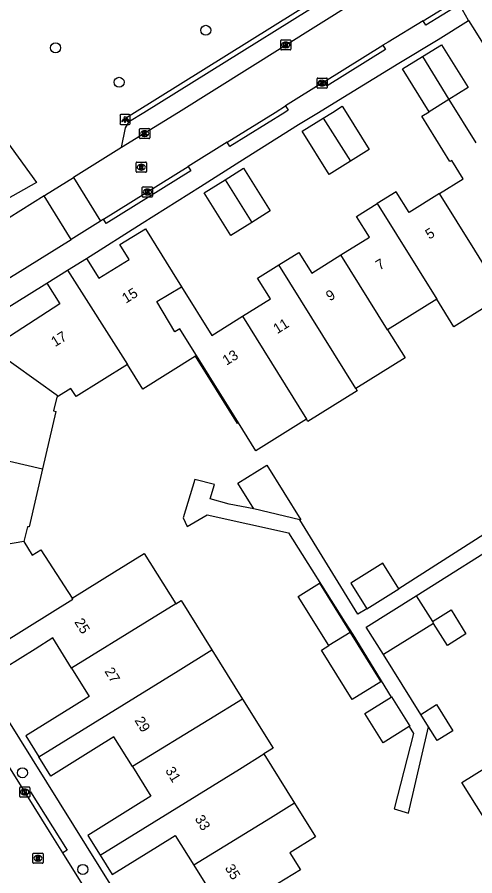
# Model space of a CAD drawing. Extents: x 157767 to 159171, y 387842 to 389425.
# Drawn here: x 158455.1 to 158500, y 387925 to 388009.4 of the extents above; entities that cross this region are included whole.
import ezdxf

# ---------------------------------------------------------------- set-up
doc = ezdxf.new("R2010")
doc.units = 0
for name, color, linetype in [('IMGEO_Boom', 7, 'Continuous'), ('IMGEO_Groenvoorziening', 7, 'Continuous'), ('IMGEO_Kolk', 7, 'Continuous'), ('IMGEO_Lichtpunt', 7, 'Continuous'), ('IMGEO_Pand', 7, 'Continuous'), ('IMGEO_Pand_nummerreeks', 7, 'Continuous'), ('IMGEO_Parkeervlak_open', 7, 'Continuous'), ('IMGEO_Rijbaan_lokaal_open', 7, 'Continuous'), ('IMGEO_Rioolput', 7, 'Continuous'), ('IMGEO_Voetpad_open', 7, 'Continuous')]:
    doc.layers.add(name, color=color, linetype=linetype)

msp = doc.modelspace()

# ---------------------------------------------------------------- linework, layer by layer
at = {"layer": 'IMGEO_Boom'}
for centre in [(158473.576, 388008.067), (158458.821, 388006.342), (158465.063, 388002.96), (158455.572, 387935.087), (158461.501, 387925.585)]:
    msp.add_circle(centre, 0.489, dxfattribs=at)
at = {"layer": 'IMGEO_Groenvoorziening'}
msp.add_lwpolyline([(158397.502, 388074.3), (158401.091, 388069.402), (158451.954, 388000), (158456.939, 387993.105), (158446.112, 387987.022)], dxfattribs=at)
at = {"layer": 'IMGEO_Kolk'}
for p, q in [((158480.933, 388006.207), (158480.933, 388007.059)), ((158481.008, 388007.133), (158481.86, 388007.133)), ((158481.934, 388007.059), (158481.934, 388006.207)), ((158481.86, 388006.133), (158481.008, 388006.133)), ((158481.444, 388006.353), (158481.419, 388006.353)), ((158481.421, 388006.913), (158481.446, 388006.913)), ((158484.504, 388002.449), (158484.504, 388003.301)), ((158484.579, 388003.375), (158485.431, 388003.375)), ((158484.992, 388003.155), (158485.017, 388003.155)), ((158485.505, 388003.301), (158485.505, 388002.449)), ((158485.431, 388002.375), (158484.579, 388002.375)), ((158485.015, 388002.595), (158484.99, 388002.595)), ((158467.073, 387997.491), (158467.073, 387998.343)), ((158467.148, 387998.417), (158468, 387998.417)), ((158467.561, 387998.197), (158467.586, 387998.197)), ((158468.074, 387998.343), (158468.074, 387997.491)), ((158468, 387997.417), (158467.148, 387997.417)), ((158467.584, 387997.637), (158467.559, 387997.637)), ((158467.342, 387991.748), (158467.342, 387992.6)), ((158467.417, 387992.674), (158468.269, 387992.674)), ((158468.343, 387992.6), (158468.343, 387991.748)), ((158467.853, 387991.894), (158467.828, 387991.894)), ((158467.83, 387992.454), (158467.855, 387992.454)), ((158468.269, 387991.674), (158467.417, 387991.674)), ((158455.301, 387932.772), (158455.301, 387933.624)), ((158455.376, 387933.698), (158456.228, 387933.698)), ((158456.302, 387933.624), (158456.302, 387932.772)), ((158456.228, 387932.698), (158455.376, 387932.698)), ((158455.812, 387932.918), (158455.787, 387932.918)), ((158455.789, 387933.478), (158455.814, 387933.478))]:
    msp.add_line(p, q, dxfattribs=at)
for points in [[(158480.933, 388006.207), (158480.933, 388007.059)], [(158481.008, 388007.133), (158481.86, 388007.133)], [(158481.934, 388007.059), (158481.934, 388006.207)], [(158481.86, 388006.133), (158481.008, 388006.133)], [(158481.254, 388006.833), (158481.377, 388006.833), (158481.377, 388006.682), (158481.507, 388006.833), (158481.671, 388006.833), (158481.525, 388006.682), (158481.678, 388006.433), (158481.526, 388006.433), (158481.441, 388006.597), (158481.377, 388006.53), (158481.377, 388006.433), (158481.254, 388006.433), (158481.254, 388006.833)], [(158484.504, 388002.449), (158484.504, 388003.301)], [(158484.579, 388003.375), (158485.431, 388003.375)], [(158484.825, 388003.075), (158484.948, 388003.075), (158484.948, 388002.924), (158485.078, 388003.075), (158485.242, 388003.075), (158485.096, 388002.924), (158485.249, 388002.675), (158485.097, 388002.675), (158485.012, 388002.839), (158484.948, 388002.772), (158484.948, 388002.675), (158484.825, 388002.675), (158484.825, 388003.075)], [(158485.505, 388003.301), (158485.505, 388002.449)], [(158485.431, 388002.375), (158484.579, 388002.375)], [(158467.073, 387997.491), (158467.073, 387998.343)], [(158467.148, 387998.417), (158468, 387998.417)], [(158467.394, 387998.117), (158467.517, 387998.117), (158467.517, 387997.966), (158467.647, 387998.117), (158467.811, 387998.117), (158467.665, 387997.966), (158467.818, 387997.717), (158467.666, 387997.717), (158467.581, 387997.881), (158467.517, 387997.814), (158467.517, 387997.717), (158467.394, 387997.717), (158467.394, 387998.117)], [(158468.074, 387998.343), (158468.074, 387997.491)], [(158468, 387997.417), (158467.148, 387997.417)], [(158467.342, 387991.748), (158467.342, 387992.6)], [(158467.417, 387992.674), (158468.269, 387992.674)], [(158468.343, 387992.6), (158468.343, 387991.748)], [(158467.663, 387992.374), (158467.786, 387992.374), (158467.786, 387992.223), (158467.916, 387992.374), (158468.08, 387992.374), (158467.934, 387992.223), (158468.087, 387991.974), (158467.935, 387991.974), (158467.85, 387992.138), (158467.786, 387992.071), (158467.786, 387991.974), (158467.663, 387991.974), (158467.663, 387992.374)], [(158468.269, 387991.674), (158467.417, 387991.674)], [(158455.301, 387932.772), (158455.301, 387933.624)], [(158455.376, 387933.698), (158456.228, 387933.698)], [(158456.302, 387933.624), (158456.302, 387932.772)], [(158456.228, 387932.698), (158455.376, 387932.698)], [(158455.622, 387933.398), (158455.745, 387933.398), (158455.745, 387933.247), (158455.875, 387933.398), (158456.039, 387933.398), (158455.893, 387933.247), (158456.046, 387932.998), (158455.894, 387932.998), (158455.809, 387933.162), (158455.745, 387933.095), (158455.745, 387932.998), (158455.622, 387932.998), (158455.622, 387933.398)]]:
    msp.add_lwpolyline(points, dxfattribs=at)
for centre, start, end in [((158481.01, 388007.057), 91.55205, 178.44795), ((158481.01, 388007.057), 91.55205, 178.44795), ((158481.858, 388007.057), 1.55205, 88.44795), ((158481.858, 388007.057), 1.55205, 88.44795), ((158481.01, 388006.209), 181.55205, 268.44795), ((158481.01, 388006.209), 181.55205, 268.44795), ((158481.858, 388006.209), 271.55205, 358.44795), ((158481.858, 388006.209), 271.55205, 358.44795), ((158484.581, 388003.299), 91.55205, 178.44795), ((158484.581, 388003.299), 91.55205, 178.44795), ((158485.429, 388003.299), 1.55205, 88.44795), ((158485.429, 388003.299), 1.55205, 88.44795), ((158484.581, 388002.451), 181.55205, 268.44795), ((158484.581, 388002.451), 181.55205, 268.44795), ((158485.429, 388002.451), 271.55205, 358.44795), ((158485.429, 388002.451), 271.55205, 358.44795), ((158467.15, 387998.341), 91.55205, 178.44795), ((158467.15, 387998.341), 91.55205, 178.44795), ((158467.998, 387998.341), 1.55205, 88.44795), ((158467.998, 387998.341), 1.55205, 88.44795), ((158467.15, 387997.493), 181.55205, 268.44795), ((158467.15, 387997.493), 181.55205, 268.44795), ((158467.998, 387997.493), 271.55205, 358.44795), ((158467.998, 387997.493), 271.55205, 358.44795), ((158467.419, 387992.598), 91.55205, 178.44795), ((158467.419, 387992.598), 91.55205, 178.44795), ((158468.267, 387992.598), 1.55205, 88.44795), ((158468.267, 387992.598), 1.55205, 88.44795), ((158467.419, 387991.75), 181.55205, 268.44795), ((158467.419, 387991.75), 181.55205, 268.44795), ((158468.267, 387991.75), 271.55205, 358.44795), ((158468.267, 387991.75), 271.55205, 358.44795), ((158455.378, 387933.622), 91.55205, 178.44795), ((158455.378, 387933.622), 91.55205, 178.44795), ((158456.226, 387933.622), 1.55205, 88.44795), ((158456.226, 387933.622), 1.55205, 88.44795), ((158455.378, 387932.774), 181.55205, 268.44795), ((158455.378, 387932.774), 181.55205, 268.44795), ((158456.226, 387932.774), 271.55205, 358.44795), ((158456.226, 387932.774), 271.55205, 358.44795)]:
    msp.add_arc(centre, 0.0765, start, end, dxfattribs=at)
for centre, major_axis, ratio, start_param, end_param in [((158481.42, 388006.633), (-0.387, 0.002), 0.722429, 4.712389, 7.853982), ((158481.445, 388006.633), (-0.39, 0.002), 0.717154, 1.570796, 4.712389), ((158484.991, 388002.875), (-0.387, 0.002), 0.722429, 4.712389, 7.853982), ((158485.016, 388002.875), (-0.39, 0.002), 0.717154, 1.570796, 4.712389), ((158467.56, 387997.917), (-0.387, 0.002), 0.722429, 4.712389, 7.853982), ((158467.585, 387997.917), (-0.39, 0.002), 0.717154, 1.570796, 4.712389), ((158467.829, 387992.174), (-0.387, 0.002), 0.722429, 4.712389, 7.853982), ((158467.854, 387992.174), (-0.39, 0.002), 0.717154, 1.570796, 4.712389), ((158455.788, 387933.198), (-0.387, 0.002), 0.722429, 4.712389, 7.853982), ((158455.813, 387933.198), (-0.39, 0.002), 0.717154, 1.570796, 4.712389)]:
    msp.add_ellipse(centre, major_axis=major_axis, ratio=ratio, start_param=start_param, end_param=end_param, dxfattribs=at)
at = {"layer": 'IMGEO_Lichtpunt'}
for p, q in [((158465.153, 387999.703), (158465.153, 387998.896)), ((158465.153, 387999.703), (158465.153, 387998.896)), ((158466.055, 387999.798), (158465.247, 387999.798)), ((158466.055, 387999.798), (158465.247, 387999.798)), ((158466.149, 387998.896), (158466.149, 387999.703)), ((158466.149, 387998.896), (158466.149, 387999.703)), ((158465.247, 387998.802), (158466.055, 387998.802)), ((158465.247, 387998.802), (158466.055, 387998.802))]:
    msp.add_line(p, q, dxfattribs=at)
for points in [[(158465.527, 387999.367), (158465.566, 387999.339), (158465.378, 387999.077), (158465.34, 387999.104), (158465.527, 387999.367)], [(158465.739, 387999.339), (158465.777, 387999.366), (158465.964, 387999.104), (158465.925, 387999.076), (158465.739, 387999.339)], [(158465.629, 387999.319), (158465.676, 387999.319), (158465.676, 387998.997), (158465.629, 387998.997), (158465.629, 387999.319)]]:
    msp.add_lwpolyline(points, dxfattribs=at)
msp.add_circle((158465.652, 387999.501), 0.0994, dxfattribs=at)
for centre, start, end in [((158465.247, 387999.703), 90, 180), ((158465.247, 387999.703), 90, 180), ((158466.055, 387999.703), 0, 90), ((158466.055, 387999.703), 0, 90), ((158465.247, 387998.896), 180, 270), ((158465.247, 387998.896), 180, 270), ((158466.055, 387998.896), 270, 0), ((158466.055, 387998.896), 270, 360)]:
    msp.add_arc(centre, 0.0946, start, end, dxfattribs=at)
at = {"layer": 'IMGEO_Pand'}
for points in [[(158494.857, 388005.499), (158496.713, 388006.654), (158499.333, 388002.445), (158497.453, 388001.275)], [(158495.503, 388000.062), (158492.883, 388004.271), (158494.857, 388005.499)], [(158494.857, 388005.499), (158497.453, 388001.275)], [(158497.453, 388001.275), (158495.503, 388000.062)], [(158497.453, 388001.275), (158500.098, 387997.004)], [(158485.099, 387999.43), (158486.014, 388000), (158486.985, 388000.604), (158487.361, 388000), (158489.631, 387996.351), (158487.779, 387995.198)], [(158487.779, 387995.198), (158485.706, 387993.908), (158483.059, 387998.161), (158485.099, 387999.43)], [(158485.099, 387999.43), (158487.779, 387995.198)], [(158496.531, 387992.022), (158498.858, 387993.471), (158497.731, 387995.282), (158497.552, 387995.171), (158494.785, 387999.616), (158495.503, 388000.062)], [(158475.481, 387993.383), (158477.298, 387994.513), (158479.913, 387990.31), (158478.115, 387989.191)], [(158478.115, 387989.191), (158476.038, 387987.899), (158473.422, 387992.102), (158475.481, 387993.383)], [(158475.481, 387993.383), (158478.115, 387989.191)], [(158496.531, 387992.022), (158493.542, 387990.16), (158492.272, 387992.199), (158490.412, 387991.04)], [(158502.799, 387981.952), (158501.119, 387984.652), (158500, 387986.449), (158496.531, 387992.022)], [(158486.857, 387985.983), (158489.653, 387987.725), (158488.378, 387989.773), (158490.412, 387991.04)], [(158490.412, 387991.04), (158496.272, 387981.633)], [(158461.851, 387985.648), (158463.067, 387983.695), (158466.041, 387985.547), (158465.137, 387986.999), (158467.647, 387988.562), (158470.284, 387984.327), (158471.197, 387982.861)], [(158480.747, 387985.003), (158482.723, 387986.234), (158483.991, 387984.198), (158486.857, 387985.983)], [(158491.436, 387978.622), (158486.857, 387985.983)], [(158460.011, 387984.502), (158461.851, 387985.648)], [(158477.194, 387979.957), (158479.939, 387981.666), (158478.667, 387983.708), (158480.747, 387985.003)], [(158488.319, 387972.861), (158480.747, 387985.003)], [(158457.961, 387983.225), (158460.011, 387984.502)], [(158460.011, 387984.502), (158465.877, 387975.202)], [(158457.961, 387983.225), (158459.229, 387981.189), (158452.509, 387976.838)], [(158476.789, 387969.5), (158471.03, 387978.74), (158470.53, 387978.44), (158468.77, 387981.42), (158471.197, 387982.861)], [(158471.197, 387982.861), (158474.176, 387978.077), (158477.194, 387979.957)], [(158496.272, 387981.633), (158491.436, 387978.622)], [(158502.799, 387981.952), (158497.953, 387978.935), (158496.272, 387981.633)], [(158477.194, 387979.957), (158483.485, 387969.841)], [(158491.436, 387978.622), (158493.15, 387975.879), (158488.319, 387972.861)], [(158452.509, 387976.838), (158459.127, 387972.116)], [(158476.789, 387969.5), (158476.683, 387969.434), (158472.575, 387976.03), (158467.381, 387972.796), (158465.877, 387975.202)], [(158465.877, 387975.202), (158460.842, 387972.067), (158460.34, 387972.872), (158459.127, 387972.116)], [(158488.319, 387972.861), (158488.451, 387972.64), (158483.616, 387969.629), (158483.485, 387969.841)], [(158459.127, 387972.116), (158458.953, 387972.008), (158458.638, 387970.655), (158458.866, 387970.602), (158457.554, 387964.961)], [(158483.485, 387969.841), (158478.509, 387966.733), (158476.789, 387969.5)], [(158446.814, 387967.458), (158457.554, 387964.961)], [(158457.554, 387964.961), (158456.229, 387959.261), (158456.053, 387959.255), (158455.719, 387957.819)], [(158478.292, 387961.019), (158476.713, 387963.559), (158479.562, 387965.339), (158482.921, 387959.935), (158482.812, 387959.961)], [(158482.812, 387959.961), (158478.292, 387961.019)], [(158455.719, 387957.819), (158447.698, 387956.443)], [(158455.719, 387957.819), (158456.527, 387956.474), (158457.389, 387957.01), (158460.458, 387952.25)], [(158460.458, 387952.25), (158464.629, 387954.847), (158467.535, 387956.657), (158470.624, 387951.696)], [(158492.529, 387953.174), (158490.968, 387955.681), (158487.824, 387953.724), (158489.385, 387951.217)], [(158485.662, 387947.593), (158482.651, 387952.428), (158484.736, 387953.726), (158487.747, 387948.891)], [(158489.385, 387951.217), (158492.529, 387953.174)], [(158451.184, 387946.354), (158460.52, 387952.15), (158460.458, 387952.25)], [(158491.018, 387946.7), (158489.328, 387949.413), (158494.254, 387952.481)], [(158494.254, 387952.481), (158495.834, 387949.944)], [(158470.624, 387951.696), (158467.83, 387949.95), (158460.391, 387945.383)], [(158470.624, 387951.696), (158471.149, 387952.025), (158474.168, 387947.177)], [(158495.834, 387949.944), (158497.674, 387951.09), (158499.131, 387948.75), (158497.306, 387947.614), (158495.945, 387949.769)], [(158495.945, 387949.769), (158491.018, 387946.7)], [(158495.834, 387949.944), (158495.945, 387949.769)], [(158487.747, 387948.891), (158490.769, 387944.038), (158487.962, 387942.291), (158484.94, 387947.143), (158485.662, 387947.593)], [(158487.747, 387948.891), (158485.662, 387947.593)], [(158460.391, 387945.383), (158458.552, 387948.336), (158456.811, 387947.252), (158452.354, 387944.476), (158451.184, 387946.354)], [(158457.17, 387936.667), (158470.85, 387945.12), (158474.168, 387947.177)], [(158474.168, 387947.177), (158477.181, 387942.339)], [(158460.391, 387945.383), (158462.129, 387942.593), (158460.374, 387941.5), (158455.897, 387938.712), (158457.17, 387936.667)], [(158477.181, 387942.339), (158473.88, 387940.29), (158466.367, 387935.69)], [(158477.181, 387942.339), (158480.192, 387937.504), (158479.28, 387936.937)], [(158493.563, 387939.625), (158490.999, 387938.028), (158489.195, 387940.924), (158491.779, 387942.533)], [(158491.779, 387942.533), (158491.826, 387942.562), (158493.629, 387939.666), (158493.563, 387939.625)], [(158494.687, 387940.828), (158496.235, 387941.793), (158497.836, 387939.222), (158496.287, 387938.258), (158495.45, 387939.602)], [(158495.45, 387939.602), (158494.687, 387940.828)], [(158466.367, 387935.69), (158464.544, 387938.617), (158462.824, 387937.546), (158458.356, 387934.763), (158457.17, 387936.667)], [(158463.201, 387927.007), (158476.9, 387935.46), (158479.28, 387936.937)], [(158479.28, 387936.937), (158482.291, 387932.102)], [(158506.376, 387921.169), (158506.692, 387921.366), (158504.915, 387924.219), (158500.887, 387930.688), (158498.738, 387934.139), (158503.829, 387937.324), (158504.051, 387936.97)], [(158466.367, 387935.69), (158468.175, 387932.786), (158466.44, 387931.706), (158461.998, 387928.939), (158463.201, 387927.007)], [(158482.291, 387932.102), (158479.93, 387930.63), (158472.4, 387926.022)], [(158482.291, 387932.102), (158484.36, 387928.78), (158481.84, 387927.21), (158482.865, 387925.563), (158479.103, 387923.26)], [(158463.201, 387927.007), (158464.397, 387925.086), (158468.831, 387927.847), (158470.584, 387928.938), (158472.4, 387926.022)], [(158472.4, 387926.022), (158474.134, 387923.237), (158472.367, 387922.137), (158467.91, 387919.361), (158469.191, 387917.305)]]:
    msp.add_lwpolyline(points, dxfattribs=at)
at = {"layer": 'IMGEO_Parkeervlak_open'}
msp.add_lwpolyline([(158465.288, 387996.548), (158465.702, 387998.489), (158466.076, 387999.127)], dxfattribs=at)
at = {"layer": 'IMGEO_Rijbaan_lokaal_open'}
for points in [[(158494.888, 388015.068), (158470.889, 388000), (158465.288, 387996.548)], [(158494.922, 388009.012), (158498.228, 388011.026)], [(158494.922, 388009.012), (158491.475, 388006.912), (158490.961, 388006.592)], [(158485.244, 388003.026), (158490.961, 388006.592)], [(158485.244, 388003.026), (158481.407, 388000.633)], [(158475.686, 387997.065), (158480.392, 388000), (158481.407, 388000.633)], [(158475.686, 387997.065), (158471.837, 387994.664)], [(158465.288, 387996.548), (158460.57, 387993.592)], [(158463.544, 387989.491), (158471.837, 387994.664)], [(158457.689, 387991.786), (158457.849, 387991.886), (158460.57, 387993.592)], [(158460.57, 387993.592), (158463.254, 387989.31)], [(158457.689, 387991.786), (158447.36, 387985.313)], [(158460.369, 387987.51), (158457.689, 387991.786)], [(158463.254, 387989.31), (158460.369, 387987.51)], [(158463.544, 387989.491), (158463.254, 387989.31)], [(158454.146, 387983.628), (158460.369, 387987.51)], [(158455.954, 387932.952), (158453.564, 387936.785)], [(158459.54, 387927.209), (158458.222, 387929.315), (158455.954, 387932.952)], [(158461.921, 387923.403), (158459.54, 387927.209)]]:
    msp.add_lwpolyline(points, dxfattribs=at)
at = {"layer": 'IMGEO_Rioolput'}
for p, q in [((158466.742, 387994.189), (158466.742, 387995.041)), ((158466.817, 387995.115), (158467.669, 387995.115)), ((158467.253, 387994.335), (158467.228, 387994.335)), ((158467.23, 387994.895), (158467.255, 387994.895)), ((158467.743, 387995.041), (158467.743, 387994.189)), ((158467.669, 387994.115), (158466.817, 387994.115)), ((158456.597, 387926.264), (158456.597, 387927.116)), ((158456.672, 387927.19), (158457.524, 387927.19)), ((158457.085, 387926.97), (158457.11, 387926.97)), ((158457.598, 387927.116), (158457.598, 387926.264)), ((158457.524, 387926.19), (158456.672, 387926.19)), ((158457.108, 387926.41), (158457.083, 387926.41))]:
    msp.add_line(p, q, dxfattribs=at)
for points in [[(158466.742, 387994.189), (158466.742, 387995.041)], [(158466.817, 387995.115), (158467.669, 387995.115)], [(158467.331, 387994.813), (158467.079, 387994.815), (158467.079, 387994.415)], [(158467.079, 387994.415), (158467.203, 387994.415), (158467.203, 387994.577), (158467.214, 387994.577)], [(158467.257, 387994.734), (158467.203, 387994.734), (158467.203, 387994.653)], [(158467.203, 387994.653), (158467.255, 387994.653)], [(158467.261, 387994.548), (158467.332, 387994.415), (158467.472, 387994.415), (158467.407, 387994.541)], [(158467.743, 387995.041), (158467.743, 387994.189)], [(158467.669, 387994.115), (158466.817, 387994.115)], [(158456.597, 387926.264), (158456.597, 387927.116)], [(158456.672, 387927.19), (158457.524, 387927.19)], [(158457.186, 387926.888), (158456.934, 387926.89), (158456.934, 387926.49)], [(158457.112, 387926.809), (158457.058, 387926.809), (158457.058, 387926.728)], [(158457.598, 387927.116), (158457.598, 387926.264)], [(158457.524, 387926.19), (158456.672, 387926.19)], [(158456.934, 387926.49), (158457.058, 387926.49), (158457.058, 387926.652), (158457.069, 387926.652)], [(158457.058, 387926.728), (158457.11, 387926.728)], [(158457.116, 387926.623), (158457.187, 387926.49), (158457.327, 387926.49), (158457.262, 387926.616)]]:
    msp.add_lwpolyline(points, dxfattribs=at)
for centre, radius, start, end in [((158466.819, 387995.039), 0.0765, 91.55205, 178.44795), ((158466.819, 387995.039), 0.0765, 91.55205, 178.44795), ((158467.213, 387994.524), 0.0533, 26.02933, 88.69889), ((158467.239, 387994.842), 0.19, 274.7715, 282.96867), ((158467.263, 387994.638), 0.0964, 77.00612, 93.18647), ((158467.277, 387994.695), 0.0378, 276.66336, 79.67722), ((158467.33, 387994.703), 0.109, 350.36119, 89.41601), ((158467.328, 387994.703), 0.112, 277.58423, 350.98172), ((158467.312, 387994.488), 0.108, 29.51342, 73.79051), ((158467.667, 387995.039), 0.0765, 1.55205, 88.44795), ((158467.667, 387995.039), 0.0765, 1.55205, 88.44795), ((158466.819, 387994.191), 0.0765, 181.55205, 268.44795), ((158466.819, 387994.191), 0.0765, 181.55205, 268.44795), ((158467.667, 387994.191), 0.0765, 271.55205, 358.44795), ((158467.667, 387994.191), 0.0765, 271.55205, 358.44795), ((158456.674, 387927.114), 0.0765, 91.55205, 178.44795), ((158456.674, 387927.114), 0.0765, 91.55205, 178.44795), ((158457.118, 387926.713), 0.0964, 77.00612, 93.18647), ((158457.132, 387926.77), 0.0378, 276.66336, 79.67722), ((158457.185, 387926.778), 0.109, 350.36119, 89.41601), ((158457.522, 387927.114), 0.0765, 1.55205, 88.44795), ((158457.522, 387927.114), 0.0765, 1.55205, 88.44795), ((158456.674, 387926.266), 0.0765, 181.55205, 268.44795), ((158456.674, 387926.266), 0.0765, 181.55205, 268.44795), ((158457.068, 387926.599), 0.0533, 26.02933, 88.69889), ((158457.094, 387926.917), 0.19, 274.7715, 282.96867), ((158457.183, 387926.778), 0.112, 277.58423, 350.98172), ((158457.167, 387926.563), 0.108, 29.51342, 73.79051), ((158457.522, 387926.266), 0.0765, 271.55205, 358.44795), ((158457.522, 387926.266), 0.0765, 271.55205, 358.44795)]:
    msp.add_arc(centre, radius, start, end, dxfattribs=at)
for centre, major_axis, ratio, start_param, end_param in [((158467.229, 387994.615), (-0.387, 0.002), 0.722429, 4.712389, 7.853982), ((158467.254, 387994.615), (-0.39, 0.002), 0.717154, 1.570796, 4.712389), ((158457.084, 387926.69), (-0.387, 0.002), 0.722429, 4.712389, 7.853982), ((158457.109, 387926.69), (-0.39, 0.002), 0.717154, 1.570796, 4.712389)]:
    msp.add_ellipse(centre, major_axis=major_axis, ratio=ratio, start_param=start_param, end_param=end_param, dxfattribs=at)
at = {"layer": 'IMGEO_Voetpad_open'}
for points in [[(158466.076, 387999.127), (158465.788, 387999.508), (158466.576, 388000), (158491.418, 388015.506), (158491.676, 388015.085)], [(158466.076, 387999.127), (158467.509, 388000), (158491.676, 388015.085)], [(158498.485, 388010.598), (158498.403, 388010.548), (158495.179, 388008.584), (158494.922, 388009.012)], [(158499.385, 388009.025), (158498.485, 388010.598)], [(158461.851, 387985.648), (158467.315, 387989.102), (158473.049, 387992.728), (158476.915, 387995.169), (158482.685, 387998.792), (158484.637, 388000), (158486.611, 388001.205), (158492.539, 388004.825), (158496.389, 388007.176), (158499.385, 388009.025)], [(158499.385, 388009.025), (158500, 388008.033), (158502.317, 388004.297), (158504.998, 388000), (158506.245, 387998.002)], [(158490.961, 388006.592), (158491.223, 388006.167), (158485.506, 388002.601), (158485.244, 388003.026)], [(158481.407, 388000.633), (158481.669, 388000.208), (158481.335, 388000), (158475.948, 387996.64), (158475.686, 387997.065)], [(158471.837, 387994.664), (158472.099, 387994.239), (158463.806, 387989.066), (158463.544, 387989.491)], [(158439.194, 387971.552), (158457.961, 387983.225)], [(158481.823, 387895.818), (158437.958, 387966.246)], [(158478.292, 387961.019), (158475.885, 387961.484), (158473.997, 387962.012), (158474.424, 387963.432), (158472.516, 387963.919), (158471.359, 387960.145), (158471.765, 387959.293), (158473.713, 387960.429), (158481.689, 387958.664), (158487.25, 387949.9), (158488.014, 387948.673), (158491.779, 387942.533)], [(158508.885, 387963.626), (158492.529, 387953.174)], [(158489.385, 387951.217), (158488.502, 387950.694), (158482.812, 387959.961)], [(158494.254, 387952.481), (158503.913, 387958.574)], [(158494.687, 387940.828), (158491.018, 387946.7)], [(158493.563, 387939.625), (158493.974, 387938.954), (158492.091, 387931.554), (158493.487, 387931.132), (158495.45, 387939.602)], [(158455.954, 387932.952), (158456.379, 387933.214), (158459.965, 387927.471), (158459.54, 387927.209)]]:
    msp.add_lwpolyline(points, dxfattribs=at)

# ---------------------------------------------------------------- texts
at = {"layer": 'IMGEO_Pand_nummerreeks'}
for s, rotation, p in [('5', 31.86791, (158495.534, 387987.481)), ('7', 31.86886, (158490.65, 387984.445)), ('15', 31.84951, (158465.738, 387981.192)), ('9', 31.86886, (158485.767, 387981.409)), ('11', 31.86886, (158480.589, 387978.191)), ('17', 31.84951, (158458.777, 387976.918)), ('13', 31.86886, (158475.608, 387975.093)), ('25', 301.43912, (158460.641, 387949.906)), ('27', 301.43912, (158463.596, 387945.073)), ('29', 301.43912, (158466.551, 387940.239)), ('31', 301.43912, (158469.565, 387935.309)), ('33', 301.43912, (158472.461, 387930.572)), ('35', 301.43798, (158475.416, 387925.738))]:
    msp.add_text(s, height=1, rotation=rotation, dxfattribs=at).set_placement(p)

doc.saveas('drawing.dxf')
